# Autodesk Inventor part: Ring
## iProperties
Created: 2005-01
Part Number: Ring
Document SubType Name: Modeling
Designer: KK
Manufacturer: Standard
Standards Organization: Custom
Description: GLAS-SIM-Ø150
Author: KK
Title: GLAS-SIM-Ø150
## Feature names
1. Drehung1 [Revolution]
